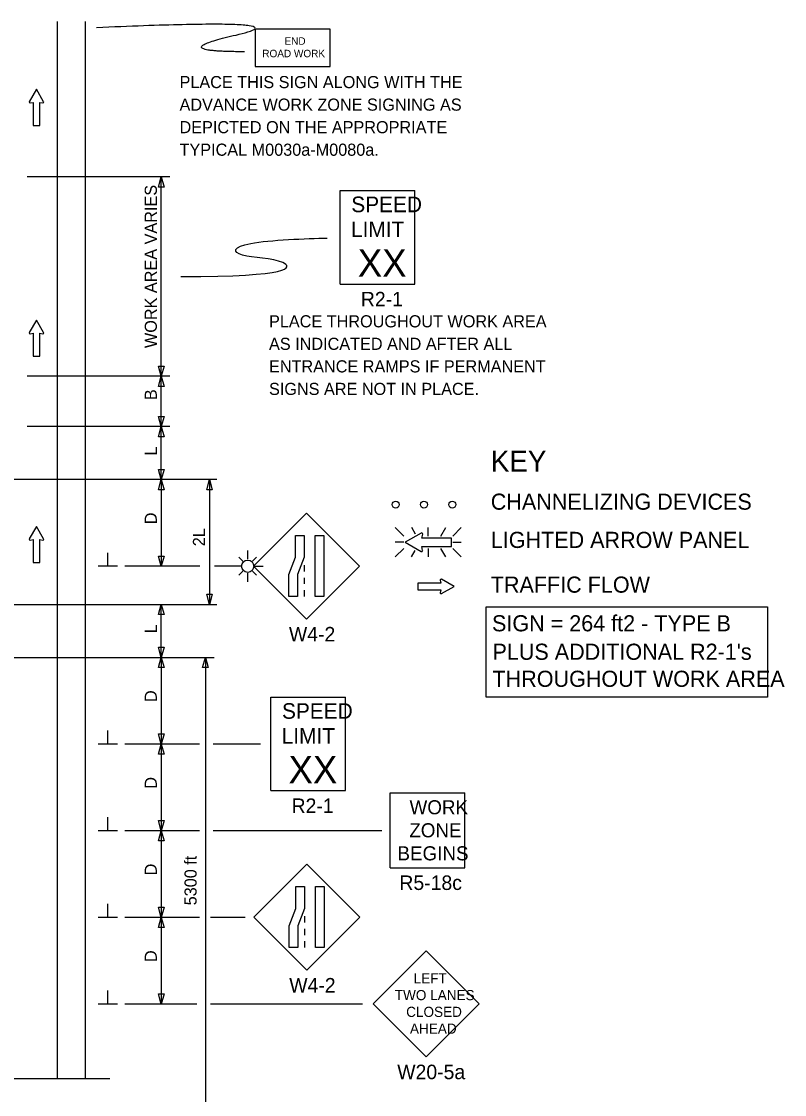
# Model space of a CAD drawing. Extents: x 16726 to 18475, y 7014 to 8214.
# Drawn here: x 16975 to 17416, y 7595 to 8214 of the extents above; entities that cross this region are included whole.
import ezdxf

# ---------------------------------------------------------------- set-up
doc = ezdxf.new("R2010")
doc.units = 0
for name, color, linetype in [('MT_SCRATCH_LEVEL_E', 7, 'Continuous'), ('PAVT_EDGE_EX', 7, 'Continuous'), ('TRAFFIC_SIGNS_PR', 7, 'Continuous'), ('TYPICAL_TEXT_DIMEN_EX', 7, 'Continuous'), ('TYPICAL_TEXT_DIMEN_PR', 7, 'Continuous')]:
    doc.layers.add(name, color=color, linetype=linetype)

msp = doc.modelspace()

# ---------------------------------------------------------------- linework, layer by layer
at = {"layer": 'MT_SCRATCH_LEVEL_E'}
for p, q in [((16983.94, 8175.21), (16979.83, 8167.97)), ((16988.09, 8167.97), (16983.94, 8175.21)), ((16980.31, 8167.29), (16982.09, 8167.6)), ((16982.09, 8167.6), (16982.09, 8154.35)), ((16985.83, 8154.35), (16985.83, 8167.6)), ((16985.83, 8167.6), (16987.61, 8167.29)), ((16982.09, 8154.35), (16985.83, 8154.35)), ((16983.94, 8042.03), (16979.83, 8034.79)), ((16988.09, 8034.79), (16983.94, 8042.03)), ((16980.31, 8034.1), (16982.09, 8034.42)), ((16982.09, 8034.42), (16982.09, 8021.16)), ((16985.83, 8021.16), (16985.83, 8034.42)), ((16985.83, 8034.42), (16987.61, 8034.1)), ((16982.09, 8021.16), (16985.83, 8021.16)), ((16983.94, 7923.03), (16979.83, 7915.78)), ((16988.09, 7915.78), (16983.94, 7923.03)), ((16980.31, 7915.1), (16982.09, 7915.41)), ((16982.09, 7915.41), (16982.09, 7902.16)), ((16985.83, 7902.16), (16985.83, 7915.41)), ((16985.83, 7915.41), (16987.61, 7915.1)), ((16982.09, 7902.16), (16985.83, 7902.16)), ((17224.92, 7888.38), (17217.68, 7892.49)), ((17217.31, 7890.23), (17204.05, 7890.23)), ((17204.05, 7890.23), (17204.05, 7886.49)), ((17204.05, 7886.49), (17217.31, 7886.49)), ((17216.99, 7892.01), (17217.31, 7890.23)), ((17217.31, 7886.49), (17216.99, 7884.71)), ((17217.68, 7884.23), (17224.92, 7888.38))]:
    msp.add_line(p, q, dxfattribs=at)
for centre, start, end in [((16980.24, 8167.75), 150.42484, 279.96381), ((16987.68, 8167.75), 260.03619, 29.77312), ((16980.24, 8034.56), 150.42484, 279.96381), ((16987.68, 8034.56), 260.03619, 29.77312), ((16980.24, 7915.56), 150.42484, 279.96381), ((16987.68, 7915.56), 260.03619, 29.77312), ((17217.45, 7892.08), 60.42484, 189.96381), ((17217.45, 7884.64), 170.03619, 299.77312)]:
    msp.add_arc(centre, 0.463, start, end, dxfattribs=at)
at = {"layer": 'PAVT_EDGE_EX'}
for p, q in [((16995.99, 8214.3), (16995.99, 7604.34)), ((17011.99, 8214.3), (17011.99, 7604.34))]:
    msp.add_line(p, q, dxfattribs=at)
at = {"layer": 'TRAFFIC_SIGNS_PR'}
for p, q in [((17159.15, 8116.81), (17202.35, 8116.81)), ((17159.15, 8062.81), (17159.15, 8116.81)), ((17202.35, 8062.81), (17202.35, 8116.81)), ((17159.15, 8062.81), (17202.35, 8062.81)), ((17139.82, 7930.64), (17109.28, 7900.09)), ((17170.37, 7900.09), (17139.82, 7930.64)), ((17190.95, 7922.39), (17195.88, 7917.46)), ((17202.71, 7918.57), (17200.5, 7922.39)), ((17210.03, 7917.46), (17210.03, 7922.39)), ((17217.27, 7917.46), (17220.12, 7922.39)), ((17224.18, 7917.46), (17229.12, 7922.39)), ((17195.88, 7913.9), (17190.95, 7913.9)), ((17224.18, 7913.9), (17229.12, 7913.9)), ((17103.02, 7902.88), (17100.65, 7905.24)), ((17105.84, 7904.05), (17105.84, 7909.11)), ((17108.66, 7902.88), (17111.03, 7905.24)), ((17190.95, 7905.41), (17195.88, 7910.34)), ((17200.46, 7905.41), (17202.57, 7909.07)), ((17210.03, 7910.34), (17210.03, 7905.41)), ((17220.16, 7905.41), (17217.31, 7910.34)), ((17224.18, 7910.34), (17229.12, 7905.41)), ((17102.3, 7900.05), (17096.86, 7900.05)), ((17109.28, 7900.09), (17139.82, 7869.54)), ((17109.38, 7900.05), (17114.87, 7900.05)), ((17138.42, 7900.64), (17138.42, 7897.04)), ((17139.82, 7869.54), (17170.37, 7900.09)), ((17103.02, 7897.23), (17100.65, 7894.86)), ((17105.84, 7891.1), (17105.84, 7896.06)), ((17108.66, 7897.23), (17111.03, 7894.86)), ((17138.42, 7893.44), (17138.42, 7889.84)), ((17138.42, 7886.24), (17138.42, 7882.64)), ((17119.17, 7824.58), (17162.37, 7824.58)), ((17119.17, 7770.58), (17119.17, 7824.58)), ((17162.37, 7770.58), (17162.37, 7824.58)), ((17119.17, 7770.58), (17162.37, 7770.58)), ((17188, 7726.16), (17188, 7769.36)), ((17188, 7769.36), (17231.2, 7769.36)), ((17231.2, 7726.16), (17231.2, 7769.36)), ((17140, 7728.11), (17109.46, 7697.56)), ((17170.55, 7697.56), (17140, 7728.11)), ((17188, 7726.16), (17231.2, 7726.16)), ((17109.46, 7697.56), (17140, 7667.01)), ((17138.6, 7698.11), (17138.6, 7694.51)), ((17140, 7667.01), (17170.55, 7697.56)), ((17138.6, 7690.91), (17138.6, 7687.31)), ((17138.6, 7683.71), (17138.6, 7680.11)), ((17208.89, 7678.11), (17178.34, 7647.56)), ((17239.43, 7647.56), (17208.89, 7678.11)), ((17178.34, 7647.56), (17208.89, 7617.01)), ((17208.89, 7617.01), (17239.43, 7647.56))]:
    msp.add_line(p, q, dxfattribs=at)
for points in [[(17110.23, 8188.32), (17153.43, 8188.32), (17153.43, 8209.92), (17110.23, 8209.92)], [(17138.42, 7917.79), (17138.42, 7905.21), (17134.66, 7895.22), (17134.66, 7882.64), (17129.6, 7882.64), (17129.6, 7895.22), (17133.36, 7905.21), (17133.36, 7917.79)], [(17149.82, 7917.79), (17149.82, 7882.64), (17144.77, 7882.64), (17144.77, 7917.79)], [(17138.6, 7715.26), (17138.6, 7702.68), (17134.84, 7692.69), (17134.84, 7680.11), (17129.78, 7680.11), (17129.78, 7692.69), (17133.54, 7702.68), (17133.54, 7715.26)], [(17150, 7715.26), (17150, 7680.11), (17144.95, 7680.11), (17144.95, 7715.26)]]:
    msp.add_lwpolyline(points, close=True, dxfattribs=at)
for points in [[(17205.96, 7919.18), (17196.67, 7913.9), (17205.96, 7908.58)], [(17206.83, 7909.21), (17206.43, 7911.47), (17223.45, 7911.47), (17223.45, 7916.28), (17206.43, 7916.28), (17206.84, 7918.56)]]:
    msp.add_lwpolyline(points, dxfattribs=at)
for centre, radius in [((17191.29, 7935.58), 2), ((17207.59, 7935.58), 2), ((17223.89, 7935.58), 2), ((17105.84, 7900.05), 3.54)]:
    msp.add_circle(centre, radius, dxfattribs=at)
for centre, radius, start, end in [((17206.25, 7918.65), 0.598, 350.73078, 118.89165), ((17206.25, 7909.1), 0.597, 241.48329, 9.95933)]:
    msp.add_arc(centre, radius, start, end, dxfattribs=at)
at = {"layer": 'TYPICAL_TEXT_DIMEN_EX'}
msp.add_lwpolyline([(17243.4, 7876.53), (17405.78, 7876.53), (17405.78, 7824.55), (17243.4, 7824.55)], close=True, dxfattribs=at)
at = {"layer": 'TYPICAL_TEXT_DIMEN_PR'}
for p, q in [((17060.99, 8124.58), (16978.59, 8124.58)), ((17054.42, 8118.72), (17055.99, 8124.58)), ((17055.99, 8009.67), (17055.99, 8124.58)), ((17055.99, 8124.58), (17057.56, 8118.72)), ((17055.99, 8118.72), (17054.42, 8118.72)), ((17057.56, 8118.72), (17055.99, 8118.72)), ((17055.99, 8009.67), (17054.42, 8015.53)), ((17054.42, 8015.53), (17055.99, 8015.53)), ((17055.99, 8015.53), (17057.56, 8015.53)), ((17057.56, 8015.53), (17055.99, 8009.67)), ((17060.99, 8009.67), (16978.59, 8009.67)), ((17054.42, 8003.81), (17055.99, 8009.67)), ((17055.99, 8003.81), (17054.42, 8003.81)), ((17055.99, 7980.62), (17055.99, 8009.67)), ((17055.99, 8009.67), (17057.56, 8003.81)), ((17057.56, 8003.81), (17055.99, 8003.81)), ((17055.99, 7980.62), (17054.42, 7986.48)), ((17054.42, 7986.48), (17055.99, 7986.48)), ((17055.99, 7986.48), (17057.56, 7986.48)), ((17057.56, 7986.48), (17055.99, 7980.62)), ((17060.99, 7980.62), (16978.59, 7980.62)), ((17054.42, 7974.75), (17055.99, 7980.62)), ((17055.99, 7950.05), (17055.99, 7980.62)), ((17055.99, 7980.62), (17057.56, 7974.75)), ((17055.99, 7974.75), (17054.42, 7974.75)), ((17057.56, 7974.75), (17055.99, 7974.75)), ((17055.99, 7950.05), (17054.42, 7955.91)), ((17054.42, 7955.91), (17055.99, 7955.91)), ((17055.99, 7955.91), (17057.56, 7955.91)), ((17057.56, 7955.91), (17055.99, 7950.05)), ((17088.03, 7950.05), (16956.89, 7950.05)), ((17054.42, 7944.19), (17055.99, 7950.05)), ((17055.99, 7950.05), (17055.99, 7900.05)), ((17055.99, 7950.05), (17057.56, 7944.19)), ((17082.22, 7944.19), (17083.79, 7950.05)), ((17083.79, 7950.05), (17085.36, 7944.19)), ((17083.79, 7950.05), (17083.79, 7878.05)), ((17055.99, 7944.19), (17054.42, 7944.19)), ((17057.56, 7944.19), (17055.99, 7944.19)), ((17083.79, 7944.19), (17082.22, 7944.19)), ((17085.36, 7944.19), (17083.79, 7944.19)), ((17025.11, 7900.05), (17025.11, 7907.84)), ((17055.99, 7900.05), (17054.42, 7905.91)), ((17054.42, 7905.91), (17055.99, 7905.91)), ((17055.99, 7905.91), (17057.56, 7905.91)), ((17057.56, 7905.91), (17055.99, 7900.05)), ((17083.79, 7904.92), (17083.79, 7901.15)), ((17030.74, 7900.05), (17019.49, 7900.05)), ((17078.23, 7900.05), (17034.99, 7900.05)), ((17102.4, 7900.05), (17086.7, 7900.05)), ((17083.79, 7878.05), (17082.22, 7883.91)), ((17082.22, 7883.91), (17083.79, 7883.91)), ((17083.79, 7883.91), (17085.36, 7883.91)), ((17085.36, 7883.91), (17083.79, 7878.05)), ((16956.89, 7878.05), (17088.03, 7878.05)), ((17054.42, 7872.19), (17055.99, 7878.05)), ((17055.99, 7847.49), (17055.99, 7878.05)), ((17055.99, 7878.05), (17057.56, 7872.19)), ((17055.99, 7872.19), (17054.42, 7872.19)), ((17057.56, 7872.19), (17055.99, 7872.19)), ((17055.99, 7847.49), (17054.42, 7853.35)), ((17054.42, 7853.35), (17055.99, 7853.35)), ((17055.99, 7853.35), (17057.56, 7853.35)), ((17057.56, 7853.35), (17055.99, 7847.49)), ((16932.38, 7847.49), (17086.42, 7847.49)), ((17054.42, 7841.63), (17055.99, 7847.49)), ((17055.99, 7847.49), (17055.99, 7797.49)), ((17055.99, 7847.49), (17057.56, 7841.63)), ((17079.85, 7841.63), (17081.42, 7847.49)), ((17081.42, 7847.49), (17081.42, 7547.49)), ((17081.42, 7847.49), (17082.99, 7841.63)), ((17055.99, 7841.63), (17054.42, 7841.63)), ((17057.56, 7841.63), (17055.99, 7841.63)), ((17081.42, 7841.63), (17079.85, 7841.63)), ((17082.99, 7841.63), (17081.42, 7841.63)), ((17025.11, 7797.49), (17025.11, 7805.27)), ((17055.99, 7797.49), (17054.42, 7803.35)), ((17054.42, 7803.35), (17055.99, 7803.35)), ((17055.99, 7803.35), (17057.56, 7803.35)), ((17057.56, 7803.35), (17055.99, 7797.49)), ((17030.74, 7797.49), (17019.49, 7797.49)), ((17077.95, 7797.49), (17034.99, 7797.49)), ((17054.42, 7791.63), (17055.99, 7797.49)), ((17055.99, 7797.49), (17055.99, 7747.49)), ((17055.99, 7797.49), (17057.56, 7791.63)), ((17113.24, 7797.49), (17085.91, 7797.49)), ((17055.99, 7791.63), (17054.42, 7791.63)), ((17057.56, 7791.63), (17055.99, 7791.63)), ((17025.11, 7747.49), (17025.11, 7755.27)), ((17055.99, 7747.49), (17054.42, 7753.35)), ((17054.42, 7753.35), (17055.99, 7753.35)), ((17055.99, 7753.35), (17057.56, 7753.35)), ((17057.56, 7753.35), (17055.99, 7747.49)), ((17030.74, 7747.49), (17019.49, 7747.49)), ((17077.95, 7747.49), (17034.99, 7747.49)), ((17054.42, 7741.63), (17055.99, 7747.49)), ((17055.99, 7747.49), (17055.99, 7697.49)), ((17055.99, 7747.49), (17057.56, 7741.63)), ((17183.19, 7747.49), (17085.91, 7747.49)), ((17055.99, 7741.63), (17054.42, 7741.63)), ((17057.56, 7741.63), (17055.99, 7741.63)), ((17025.11, 7697.49), (17025.11, 7705.27)), ((17055.99, 7697.49), (17054.42, 7703.35)), ((17054.42, 7703.35), (17055.99, 7703.35)), ((17055.99, 7703.35), (17057.56, 7703.35)), ((17057.56, 7703.35), (17055.99, 7697.49)), ((17030.74, 7697.49), (17019.49, 7697.49)), ((17077.95, 7697.49), (17034.99, 7697.49)), ((17054.42, 7691.63), (17055.99, 7697.49)), ((17055.99, 7697.49), (17055.99, 7647.49)), ((17055.99, 7697.49), (17057.56, 7691.63)), ((17104.49, 7697.49), (17084.45, 7697.49)), ((17055.99, 7691.63), (17054.42, 7691.63)), ((17057.56, 7691.63), (17055.99, 7691.63)), ((17025.11, 7647.49), (17025.11, 7655.27)), ((17055.99, 7647.49), (17054.42, 7653.35)), ((17054.42, 7653.35), (17055.99, 7653.35)), ((17055.99, 7653.35), (17057.56, 7653.35)), ((17057.56, 7653.35), (17055.99, 7647.49)), ((17030.74, 7647.49), (17019.49, 7647.49)), ((17076.53, 7647.49), (17034.99, 7647.49)), ((17172.04, 7647.49), (17084.48, 7647.49)), ((17026.32, 7604.34), (16963.98, 7604.34))]:
    msp.add_line(p, q, dxfattribs=at)
for points, degree in [([(17103.97, 8196.84), (17056.73, 8196.84), (17141.76, 8216.18), (17018.66, 8210.69)], 2), ([(17067.36, 8067.13), (17131.94, 8067.13), (17131.94, 8077.88), (17097.02, 8077.88), (17097.02, 8087.54), (17139.88, 8089.06), (17151.79, 8089.32)], 3)]:
    msp.add_open_spline(points, degree=degree, dxfattribs=at)

# ---------------------------------------------------------------- texts
at = {"layer": 'TRAFFIC_SIGNS_PR'}
for s, height, p in [('END', 4.31, (17127.1, 8200.84)), ('ROAD WORK', 4.31, (17114.29, 8193.66)), ('PLACE THIS SIGN ALONG WITH THE', 7, (17066.52, 8175.83)), ('ADVANCE WORK ZONE SIGNING AS', 7, (17066.52, 8162.83)), ('DEPICTED ON THE APPROPRIATE', 7, (17066.52, 8149.83)), ('TYPICAL M0030a-M0080a.', 7, (17066.52, 8136.83)), ('SPEED', 9, (17165.64, 8104.28)), ('LIMIT', 9, (17165.46, 8089.88)), ('XX', 15.785, (17169.4, 8067.03)), ('R2-1', 8.37, (17171.16, 8049.94)), ('PLACE THROUGHOUT WORK AREA', 7, (17118.16, 8037.84)), ('AS INDICATED AND AFTER ALL', 7, (17118.16, 8024.84)), ('ENTRANCE RAMPS IF PERMANENT', 7, (17118.16, 8011.84)), ('SIGNS ARE NOT IN PLACE.', 7, (17118.16, 7998.84)), ('W4-2', 8.37, (17129.65, 7856.67)), ('SPEED', 9, (17125.65, 7812.05)), ('LIMIT', 9, (17125.47, 7797.65)), ('XX', 15.785, (17129.42, 7774.81)), ('R2-1', 8.37, (17131.18, 7757.71)), ('WORK', 8.119, (17199.25, 7756.95)), ('ZONE', 8.119, (17199.11, 7743.67)), ('BEGINS', 8.119, (17192.28, 7730.38)), ('R5-18c', 8.37, (17193.41, 7713.29)), ('LEFT', 5.85, (17201.62, 7659.41)), ('W4-2', 8.37, (17129.83, 7654.14)), ('TWO LANES', 5.85, (17190.73, 7649.73)), ('CLOSED', 5.85, (17197.31, 7640.06)), ('AHEAD', 5.85, (17199.5, 7630.38)), ('W20-5a', 8.37, (17192.17, 7604.14))]:
    msp.add_text(s, height=height, dxfattribs=at).set_placement(p)
at = {"layer": 'TYPICAL_TEXT_DIMEN_EX'}
for s, height, p in [('KEY', 12, (17246.13, 7954.69)), ('CHANNELIZING DEVICES', 9.3, (17246.13, 7932.64)), ('LIGHTED ARROW PANEL', 9.3, (17246.13, 7910.59)), ('TRAFFIC FLOW', 9.3, (17246.13, 7884.79)), ('SIGN = 264 ft2 - TYPE B', 9.3, (17246.84, 7862.49)), ("PLUS ADDITIONAL R2-1's", 9.3, (17247.12, 7846.07)), ('THROUGHOUT WORK AREA', 9.3, (17247.12, 7830.47))]:
    msp.add_text(s, height=height, dxfattribs=at).set_placement(p)
at = {"layer": 'TYPICAL_TEXT_DIMEN_PR'}
for s, p in [('WORK AREA VARIES', (17053.43, 8025.89)), ('B', (17053.43, 7995.88)), ('L', (17053.43, 7963.91)), ('D', (17053.43, 7924.27)), ('2L', (17081.23, 7911.55)), ('L', (17053.43, 7861.34)), ('D', (17053.43, 7821.71)), ('D', (17053.43, 7771.71)), ('5300 ft', (17076.38, 7704.43)), ('D', (17053.43, 7721.71)), ('D', (17053.43, 7671.71))]:
    msp.add_text(s, height=7, rotation=90, dxfattribs=at).set_placement(p)

doc.saveas('drawing.dxf')
